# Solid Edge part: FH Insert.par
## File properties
Author: Dave
Template: Normal.par
Last saved by: Dave
Revision: 17
Application: Solid Edge
Accuracy: 0.990
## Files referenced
..\Mould Assy.asm
EC:\drawings\DK laminates\Squared Leg Foot\ToolDrawings\Mould Assy.asm
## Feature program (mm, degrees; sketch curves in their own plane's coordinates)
sketch for "unnamed Protrusion 1" plane through (0, 0, 0) normal (0, 0, 1) x-axis (1, 0, 0)
  line (-24.1487, 24.1487) -> (-24.1487, -24.1487)
  line (-24.1487, -24.1487) -> (24.1487, -24.1487)
  line (24.1487, -24.1487) -> (24.1487, -11.8309)
  line (24.1487, -11.8309) -> (-11.8309, 24.1487)
  line (-11.8309, 24.1487) -> (-24.1487, 24.1487)
extrude "unnamed Protrusion 1" add finite 46 along +normal
boolean "unnamed Boolean 1"
delete faces "unnamed DeleteFaces 1"
sketch for "Hole_1" plane through (0, 0, 0) normal (0, 0, -1) x-axis (-1, 0, 0)
  hole centre (18.1487, -18.1487) bore radius 2.4585
hole "Hole_1" finite  VBottomAngle = 118 deg; ThreadDepth = 15 mm
sketch for "unnamed Hole 1" plane through (0, 0, 0) normal (0, 0, -1) x-axis (-1, 0, 0)
  hole centre (18.1487, 18.1487) bore radius 2.4585
hole "unnamed Hole 1" finite
sketch for "unnamed Hole 2" plane through (0, 0, 0) normal (0, 0, -1) x-axis (-1, 0, 0)
  hole centre (-18.1487, -18.1487) bore radius 2.4585
hole "unnamed Hole 2" finite
pattern "unnamed Pattern 1" of "Hole_1", "unnamed Hole 1", "unnamed Hole 2"
sketch for "Hole_4" plane through (0, 0, 0) normal (0, 0, -1) x-axis (0, -1, 0)
  hole centre (10.1487, 4) bore radius 9
hole "Hole_4" diameter 18 finite  CounterBoreDepth = 1.8 mm
sketch for "Hole_5" plane through (-3, -10.1487, 18) normal (0, 0, -1) x-axis (1, 0, 0)
  hole centre (-1, 0) bore radius 3
hole "Hole_5" diameter 6 finite  VBottomAngle = 118 deg
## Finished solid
Body 1: solid body, 252 faces, 528 edges, 282 vertices.
  Faces by surface: cylinder 102, spline 48, plane 43, sphere 38, torus 16, cone 5
  Edges by curve: line 200, circle 168, curve on surface 124, ellipse 26, spline 10
Body 2: solid body, 62 faces, 118 edges, 59 vertices.
  Faces by surface: cylinder 23, plane 16, spline 9, sphere 7, cone 5, torus 2
  Edges by curve: line 49, circle 37, curve on surface 25, ellipse 5, spline 2
Bounding box of the edges (mm; curved faces can reach further): 61.690 x 61.690 x 60.620, from (-33.2567, -33.2567, 0) to (28.4329, 28.4329, 60.62).
Cylindrical faces by radius (mm): R0.504 x113, R1.008 x4, R2.4585 x3, R3 x1, R4.2235 x1, R7.2475 x1, R9 x1, R11 x1
Conical faces (half-angle, radius in mm at the cone's reference point): 1 deg R7.056 x2, 1 deg R20.412 x1, 1 deg R23.436 x3, 59 deg R2.4585 x3, 59 deg R3 x1
Toroidal faces (ring radius, tube radius in mm): R0.504 r0.504 x3, R1.512 r0.504 x1, R6.1209 r0.504 x2, R6.7435 r0.504 x1, R7.5513 r0.504 x2, R7.7515 r0.504 x1, R19.9167 r0.504 x1, R21.1184 r0.504 x1, R22.7296 r0.504 x3, R23.9313 r0.504 x3
Spherical faces by radius (mm): R0.504 x45
Planar faces by outward normal: +x 2, +y 2, +z 9, -x 3, -y 3, -z 6, oblique 34
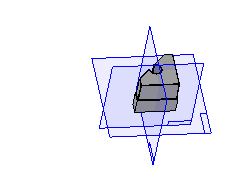
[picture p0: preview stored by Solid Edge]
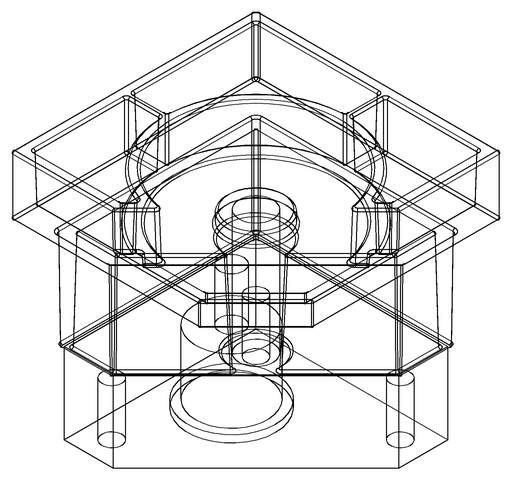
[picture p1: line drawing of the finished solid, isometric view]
